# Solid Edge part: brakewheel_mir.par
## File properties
Author: KULL
Template: Iso Metric Part.par
Last saved by: KULL
Revision: 2
Application: Solid Edge
Accuracy: 0,990
Username: KULL
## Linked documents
brakewheel.par
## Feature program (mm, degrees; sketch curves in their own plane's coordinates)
part copy "CopiedPart_1"
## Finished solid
Body 1: solid body, 544 faces, 1066 edges, 432 vertices.
  Faces by surface: torus 226, cylinder 204, blend 72, plane 42
  Edges by curve: circle 742, intersection 216, line 108
Bounding box of the edges (mm; curved faces can reach further): 52.000 x 5.000 x 52.000, from (-26, -123, -3) to (26, -118, 49).
Cylindrical faces by radius (mm): R0.2 x36, R0.7 x36, R0.8 x36, R0.9 x36, R4 x1, R10 x2, R14.7173 x18, R15 x2, R17 x18, R26 x1, R28.4 x18
Toroidal faces (ring radius, tube radius in mm): R0.8 r0.1 x36, R0.9 r0.1 x36, R1 r0.1 x36, R9.8 r0.2 x2, R10.2 r0.2 x2, R14.8 r0.2 x2, R15.1173 r0.4 x36, R15.2 r0.2 x2, R25.8 r0.2 x38, R28 r0.4 x36
Planar faces by outward normal: +y 21, -y 21
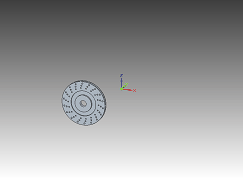
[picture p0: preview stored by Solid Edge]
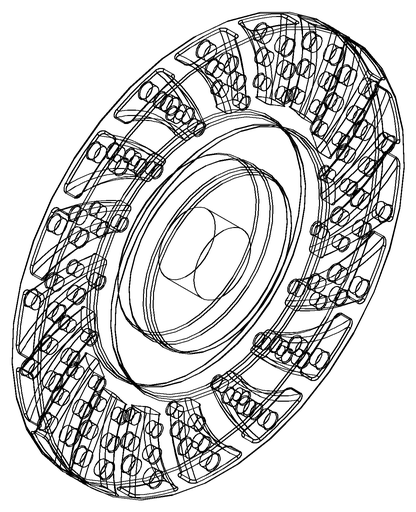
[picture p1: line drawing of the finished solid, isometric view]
